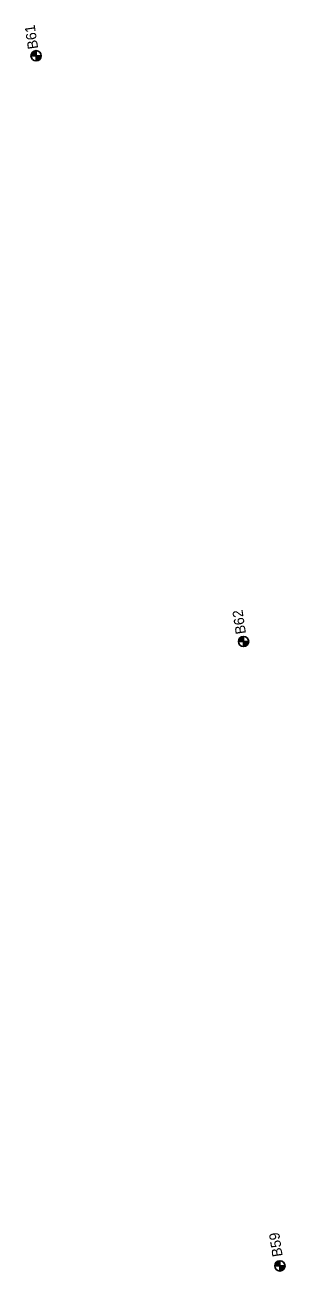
# Model space of a CAD drawing. Extents: x 335726 to 369746, y 119154 to 200788.
# Drawn here: x 359449 to 359702, y 162875 to 164088 of the extents above; entities that cross this region are included whole.
import ezdxf

# ---------------------------------------------------------------- set-up
doc = ezdxf.new("R2010")
doc.units = 0
doc.layers.add('E_SOIL_BORE2 [KAPUR_CADDS_LEVELS]', color=7, linetype='Continuous')
doc.layers.add('P_MARK', color=7, linetype='Continuous')

msp = doc.modelspace()

# ---------------------------------------------------------------- linework, layer by layer
at = {"layer": 'P_MARK'}
for p, q in [((359459.6, 164063.3), (359459.6, 164053.3)), ((359454.6, 164058.3), (359464.6, 164058.3)), ((359661.6, 163492.9), (359661.6, 163482.9)), ((359656.6, 163487.9), (359666.6, 163487.9)), ((359692, 162879.9), (359702, 162879.9)), ((359697, 162884.9), (359697, 162874.9))]:
    msp.add_line(p, q, dxfattribs=at)
for centre in [(359459.6, 164058.3), (359661.6, 163487.9), (359697, 162879.9)]:
    msp.add_circle(centre, 5, dxfattribs=at)
for centre, radius, start, end in [((359459.6, 164058.3), 4.5, 89.9869, 179.9869), ((359459.6, 164058.3), 4, 89.9869, 179.9869), ((359459.6, 164058.3), 3.5, 89.9869, 179.9869), ((359459.6, 164058.3), 3, 89.9869, 179.9869), ((359459.6, 164058.3), 2.5, 89.9869, 179.9869), ((359459.6, 164058.3), 2, 89.9869, 179.9869), ((359459.6, 164058.3), 1.5, 89.9869, 179.9869), ((359459.6, 164058.3), 1, 89.9869, 179.9869), ((359459.6, 164058.3), 0.5, 89.9869, 179.9869), ((359459.6, 164058.3), 4.5, 269.9869, 359.9869), ((359459.6, 164058.3), 4, 269.9869, 359.9869), ((359459.6, 164058.3), 3.5, 269.9869, 359.9869), ((359459.6, 164058.3), 3, 269.9869, 359.9869), ((359459.6, 164058.3), 2.5, 269.9869, 359.9869), ((359459.6, 164058.3), 2, 269.9869, 359.9869), ((359459.6, 164058.3), 1.5, 269.9869, 359.9869), ((359459.6, 164058.3), 1, 269.9869, 359.9869), ((359459.6, 164058.3), 0.5, 269.9869, 359.9869), ((359661.6, 163487.9), 4.5, 89.9869, 179.9869), ((359661.6, 163487.9), 4, 89.9869, 179.9869), ((359661.6, 163487.9), 3.5, 89.9869, 179.9869), ((359661.6, 163487.9), 3, 89.9869, 179.9869), ((359661.6, 163487.9), 2.5, 89.9869, 179.9869), ((359661.6, 163487.9), 2, 89.9869, 179.9869), ((359661.6, 163487.9), 1.5, 89.9869, 179.9869), ((359661.6, 163487.9), 1, 89.9869, 179.9869), ((359661.6, 163487.9), 0.5, 89.9869, 179.9869), ((359661.6, 163487.9), 4.5, 269.9869, 359.9869), ((359661.6, 163487.9), 4, 269.9869, 359.9869), ((359661.6, 163487.9), 3.5, 269.9869, 359.9869), ((359661.6, 163487.9), 3, 269.9869, 359.9869), ((359661.6, 163487.9), 2.5, 269.9869, 359.9869), ((359661.6, 163487.9), 2, 269.9869, 359.9869), ((359661.6, 163487.9), 1.5, 269.9869, 359.9869), ((359661.6, 163487.9), 1, 269.9869, 359.9869), ((359661.6, 163487.9), 0.5, 269.9869, 359.9869), ((359697, 162879.9), 4.5, 89.9869, 179.9869), ((359697, 162879.9), 4, 89.9869, 179.9869), ((359697, 162879.9), 3.5, 89.9869, 179.9869), ((359697, 162879.9), 3, 89.9869, 179.9869), ((359697, 162879.9), 2.5, 89.9869, 179.9869), ((359697, 162879.9), 2, 89.9869, 179.9869), ((359697, 162879.9), 1.5, 89.9869, 179.9869), ((359697, 162879.9), 1, 89.9869, 179.9869), ((359697, 162879.9), 0.5, 89.9869, 179.9869), ((359697, 162879.9), 4.5, 269.9869, 359.9869), ((359697, 162879.9), 4, 269.9869, 359.9869), ((359697, 162879.9), 3.5, 269.9869, 359.9869), ((359697, 162879.9), 3, 269.9869, 359.9869), ((359697, 162879.9), 2.5, 269.9869, 359.9869), ((359697, 162879.9), 2, 269.9869, 359.9869), ((359697, 162879.9), 1.5, 269.9869, 359.9869), ((359697, 162879.9), 1, 269.9869, 359.9869), ((359697, 162879.9), 0.5, 269.9869, 359.9869)]:
    msp.add_arc(centre, radius, start, end, dxfattribs=at)

# ---------------------------------------------------------------- texts
at = {"layer": 'E_SOIL_BORE2 [KAPUR_CADDS_LEVELS]'}
for s, p in [('B61', (359461.7, 164065.5)), ('B62', (359664, 163495.8)), ('B59', (359699.7, 162889.5))]:
    msp.add_text(s, height=10, rotation=98.5151, dxfattribs=at).set_placement(p)

doc.saveas('drawing.dxf')
